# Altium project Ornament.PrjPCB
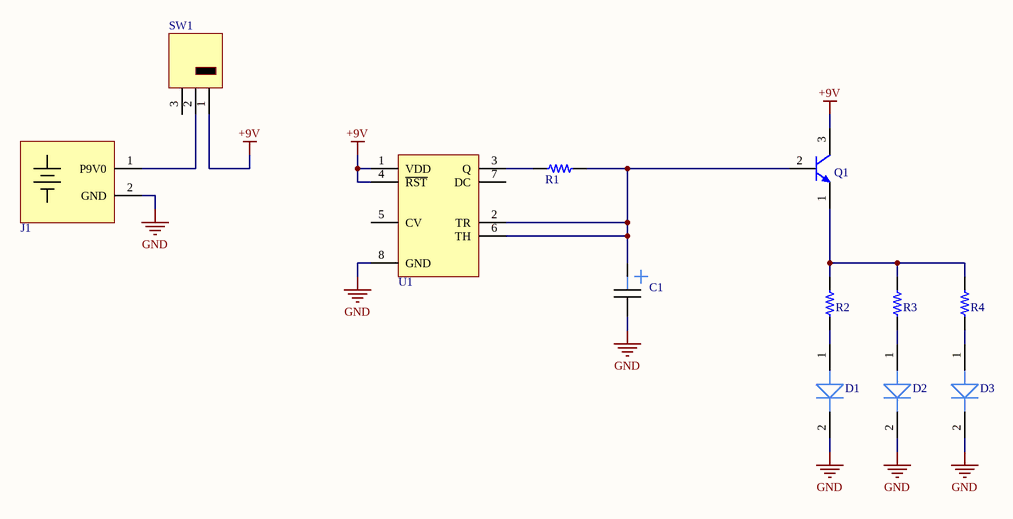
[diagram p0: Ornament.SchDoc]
1 sheet, 12 parts. Net scope: global (net labels, ports and power ports of the same name join across sheets).
Board file: Ornament.PcbDoc

## Sheet Ornament.SchDoc: Twinkle Twinkle Little Star
size B; Author: Brady Salz; Organization: Astranis; Address1: 420 Bryant St.; Address2: San Francisco, CA; DocumentNumber: 1; Revision: 01; SheetNumber: 1; SheetTotal: 1

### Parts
C1  CAP TH ELECTRO  [CAP ELELCTROLYTIC TH]  (value not drawn)
D1  Blue LED  [BLUE_LED]  (value not drawn)
D2  Blue LED  [BLUE_LED]  (value not drawn)
D3  Blue LED  [BLUE_LED]  (value not drawn)
J1  BATT HOLDER 9V  [BH9VW]  (value not drawn)
Q1  PN2222TA  [BJT NPN]  (value not drawn)
R1  RES TH  [RES TH]  (value not drawn)
R2  RES TH  [RES TH]  (value not drawn)
R3  RES TH  [RES TH]  (value not drawn)
R4  RES TH  [RES TH]  (value not drawn)
SW1  OS102011MS2QS1  [SPDT SW]  (value not drawn)
U1  NE555  [555 SOCKET]  (value not drawn)

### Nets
+9V: Q1.3(C) SW1.1 U1.1(VDD) U1.4(~{RST})
GND: C1.2 D1.2 D2.2 D3.2 J1.2(GND) U1.8(GND)
NetC1_1: C1.1 Q1.2(B) R1.1 U1.2(TR) U1.6(TH)
NetD1_1: D1.1 R2.2
NetD2_1: D2.1 R3.2
NetD3_1: D3.1 R4.2
NetJ1_1: J1.1(P9V0) SW1.2
NetQ1_1: Q1.1(E) R2.1 R3.1 R4.1
NetR1_2: R1.2 U1.3(Q)

Not connected (* = marked no-connect by the designer): SW1 3; U1 5(CV) 7(DC)

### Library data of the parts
D1-D3 = Blue_LED: MPN: 3474AN-BADB-AGJA-PR-MS; Vfwd: 3.2
J1 = BH9VW: BATTERY HOLDER 9V 6" LEADS
Q1 = BJT NPN
SW1 = SPDT SW
U1 = NE555: MPN: NE555P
